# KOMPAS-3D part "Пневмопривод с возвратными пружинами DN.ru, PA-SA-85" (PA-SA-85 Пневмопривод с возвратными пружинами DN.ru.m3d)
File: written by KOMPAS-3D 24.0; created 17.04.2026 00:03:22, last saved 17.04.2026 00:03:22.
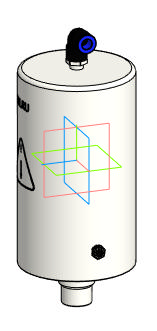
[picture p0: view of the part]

Document properties: Автор: DN.RU; Полное имя файла: D:\PROJECT CAD\DN.RU\...201(ACTUALE). PA-SA-85 Пневмопривод с возвратными пружинами DN.ru\Исходники\Шток 8мм\PA-SA-85 Пневмопривод с возвратными пружинами DN.ru.m3d

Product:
- Body: Твердое тело2  | qty 1
    Масса: 6.656936
- Part/product: Пневмопривод с возвратными пружинами DN.ru  | designation PA-SA-85
    Масса: 3.09
    Раздел спецификации: Прочие изделия
    Комментарий: D290-00341
    Примечание: D290-00341
    additional columns: Типовые

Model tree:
1. Твердое тело2  (labels: Твердое тело2)

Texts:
  PA-SA-85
